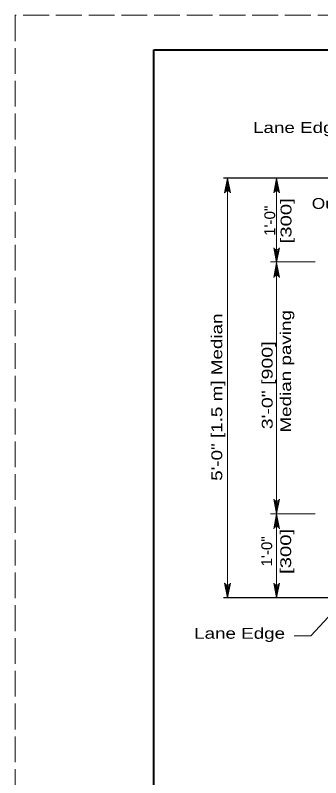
# Model space of a CAD drawing. Extents: x 339.1 to 373.1, y 1412.7 to 1456.7.
# Drawn here: x 339.06 to 343.47, y 1445.77 to 1456.75 of the extents above; entities that cross this region are included whole.
import ezdxf
from ezdxf.enums import TextEntityAlignment as Align

# ---------------------------------------------------------------- set-up
doc = ezdxf.new("R2010")
doc.units = 0
doc.header["$LTSCALE"] = 0.062
doc.linetypes.add('LONG_DASHED', pattern=[7.5, 6, -1.5])
doc.layers.add('1', color=7, linetype='Continuous', lineweight=13)

msp = doc.modelspace()

# ---------------------------------------------------------------- linework, layer by layer
at = {"layer": '1', "lineweight": 25}
for p, q in [((341.0605, 1456.2455), (372.5605, 1456.2455)), ((346.37042, 1454.40183), (342.06367, 1454.40183)), ((344.55492, 1448.35533), (342.06367, 1448.35533))]:
    msp.add_line(p, q, dxfattribs=at)
at = {"layer": '1'}
for p, q in [((342.09442, 1454.20567), (342.12442, 1454.40183)), ((342.107, 1454.21308), (342.12442, 1454.40183)), ((342.12442, 1454.2165), (342.12442, 1454.40183)), ((342.13808, 1454.2145), (342.12442, 1454.40183)), ((342.1515, 1454.20792), (342.12442, 1454.40183)), ((342.12442, 1454.40183), (342.12442, 1448.35533)), ((342.80242, 1454.20567), (342.83242, 1454.40183)), ((342.815, 1454.21308), (342.83242, 1454.40183)), ((342.83242, 1454.2165), (342.83242, 1454.40183)), ((342.84608, 1454.2145), (342.83242, 1454.40183)), ((342.8595, 1454.20792), (342.83242, 1454.40183)), ((342.83242, 1454.40183), (342.83242, 1448.35533)), ((342.80525, 1453.37675), (342.83242, 1453.18283)), ((342.81867, 1453.37017), (342.83242, 1453.18283)), ((342.86242, 1453.379), (342.83242, 1453.18283)), ((342.84983, 1453.37158), (342.83242, 1453.18283)), ((342.83242, 1453.36817), (342.83242, 1453.18283)), ((343.387, 1453.1925), (342.74417, 1453.1925)), ((342.80242, 1452.98667), (342.83242, 1453.18283)), ((342.815, 1452.99408), (342.83242, 1453.18283)), ((342.83242, 1452.9975), (342.83242, 1453.18283)), ((342.84608, 1452.9955), (342.83242, 1453.18283)), ((342.8595, 1452.98892), (342.83242, 1453.18283)), ((342.80525, 1449.7585), (342.83242, 1449.56467)), ((342.81867, 1449.75192), (342.83242, 1449.56467)), ((342.86242, 1449.76083), (342.83242, 1449.56467)), ((342.84983, 1449.75342), (342.83242, 1449.56467)), ((342.83242, 1449.74992), (342.83242, 1449.56467)), ((343.387, 1449.56467), (342.74417, 1449.56467)), ((342.80242, 1449.36842), (342.83242, 1449.56467)), ((342.815, 1449.37583), (342.83242, 1449.56467)), ((342.83242, 1449.37933), (342.83242, 1449.56467)), ((342.84608, 1449.37733), (342.83242, 1449.56467)), ((342.8595, 1449.37075), (342.83242, 1449.56467)), ((342.09725, 1448.54925), (342.12442, 1448.35533)), ((342.11067, 1448.54267), (342.12442, 1448.35533)), ((342.15442, 1448.5515), (342.12442, 1448.35533)), ((342.14183, 1448.54408), (342.12442, 1448.35533)), ((342.12442, 1448.54067), (342.12442, 1448.35533)), ((342.80525, 1448.54925), (342.83242, 1448.35533)), ((342.81867, 1448.54267), (342.83242, 1448.35533)), ((342.86242, 1448.5515), (342.83242, 1448.35533)), ((342.84983, 1448.54408), (342.83242, 1448.35533)), ((342.83242, 1448.54067), (342.83242, 1448.35533))]:
    msp.add_line(p, q, dxfattribs=at)
at = {"layer": '1', "linetype": 'LONG_DASHED'}
msp.add_lwpolyline([(339.0605, 1434.7455), (373.0605, 1434.7455), (373.0605, 1456.7455), (339.0605, 1456.7455)], close=True, dxfattribs=at)
at = {"layer": '1', "lineweight": 25}
msp.add_lwpolyline([(372.5605, 1435.2455), (341.0605, 1435.2455), (341.0605, 1456.2455)], dxfattribs=at)
at = {"layer": '1', "lineweight": 40}
msp.add_lwpolyline([(341.0605, 1456.2455), (372.5605, 1456.2455), (372.5605, 1435.2455), (341.0605, 1435.2455)], close=True, dxfattribs=at)
at = {"layer": '1'}
for points in [[(342.08158, 1454.18767), (342.12442, 1454.40183), (342.16725, 1454.18767)], [(342.78958, 1454.18767), (342.83242, 1454.40183), (342.87525, 1454.18767)], [(342.87525, 1453.397), (342.83242, 1453.18283), (342.78958, 1453.397)], [(342.78958, 1452.96867), (342.83242, 1453.18283), (342.87525, 1452.96867)], [(342.87525, 1449.77883), (342.83242, 1449.56467), (342.78958, 1449.77883)], [(342.78958, 1449.3505), (342.83242, 1449.56467), (342.87525, 1449.3505)], [(342.16725, 1448.5695), (342.12442, 1448.35533), (342.08158, 1448.5695)], [(342.87525, 1448.5695), (342.83242, 1448.35533), (342.78958, 1448.5695)], [(343.83583, 1448.35708), (343.32525, 1447.80808), (343.08417, 1447.80808)]]:
    msp.add_lwpolyline(points, dxfattribs=at)
for centre, start, end in [((342.12444, 1454.17038), 22.08782, 157.91395), ((342.83245, 1454.17038), 22.08782, 157.91395), ((342.83235, 1453.4143), 202.08782, 337.91395), ((342.83245, 1452.95137), 22.08782, 157.91395), ((342.83235, 1449.79609), 202.08782, 337.91395), ((342.83245, 1449.33316), 22.08782, 157.91395), ((342.12435, 1448.58679), 202.08782, 337.91395), ((342.83235, 1448.58679), 202.08782, 337.91395)]:
    msp.add_arc(centre, 0.04623, start, end, dxfattribs=at)

# ---------------------------------------------------------------- texts
for s, width, p in [('Lane Edge', 1.3, (342.49183, 1455.05033)), ('Outlet pipe', 1.2, (343.33858, 1453.95683)), ('Lane Edge', 1.3, (341.64175, 1447.76708))]:
    msp.add_text(s, height=0.156, dxfattribs=dict(at, width=width)).set_placement(p)
for s, width, p in [('[300]', 1.4, (343.04558, 1453.78571)), ('1\'-0"', 1.05, (342.81092, 1453.78575)), ('[300]', 1.4, (343.04117, 1449.02487)), ('1\'-0"', 1.05, (342.76717, 1449.02492))]:
    msp.add_text(s, height=0.156, rotation=90, dxfattribs=dict(at, width=width)).set_placement(p, align=Align.CENTER)
for s, width, p in [('Median paving', 1.3, (343.04058, 1450.736)), ('5\'-0" [1.5 m] Median', 1.3, (342.04642, 1450.04175)), ('3\'-0" [900]', 1.35, (342.77442, 1450.78358))]:
    msp.add_text(s, height=0.156, rotation=90, dxfattribs=dict(at, width=width)).set_placement(p)

doc.saveas('drawing.dxf')
